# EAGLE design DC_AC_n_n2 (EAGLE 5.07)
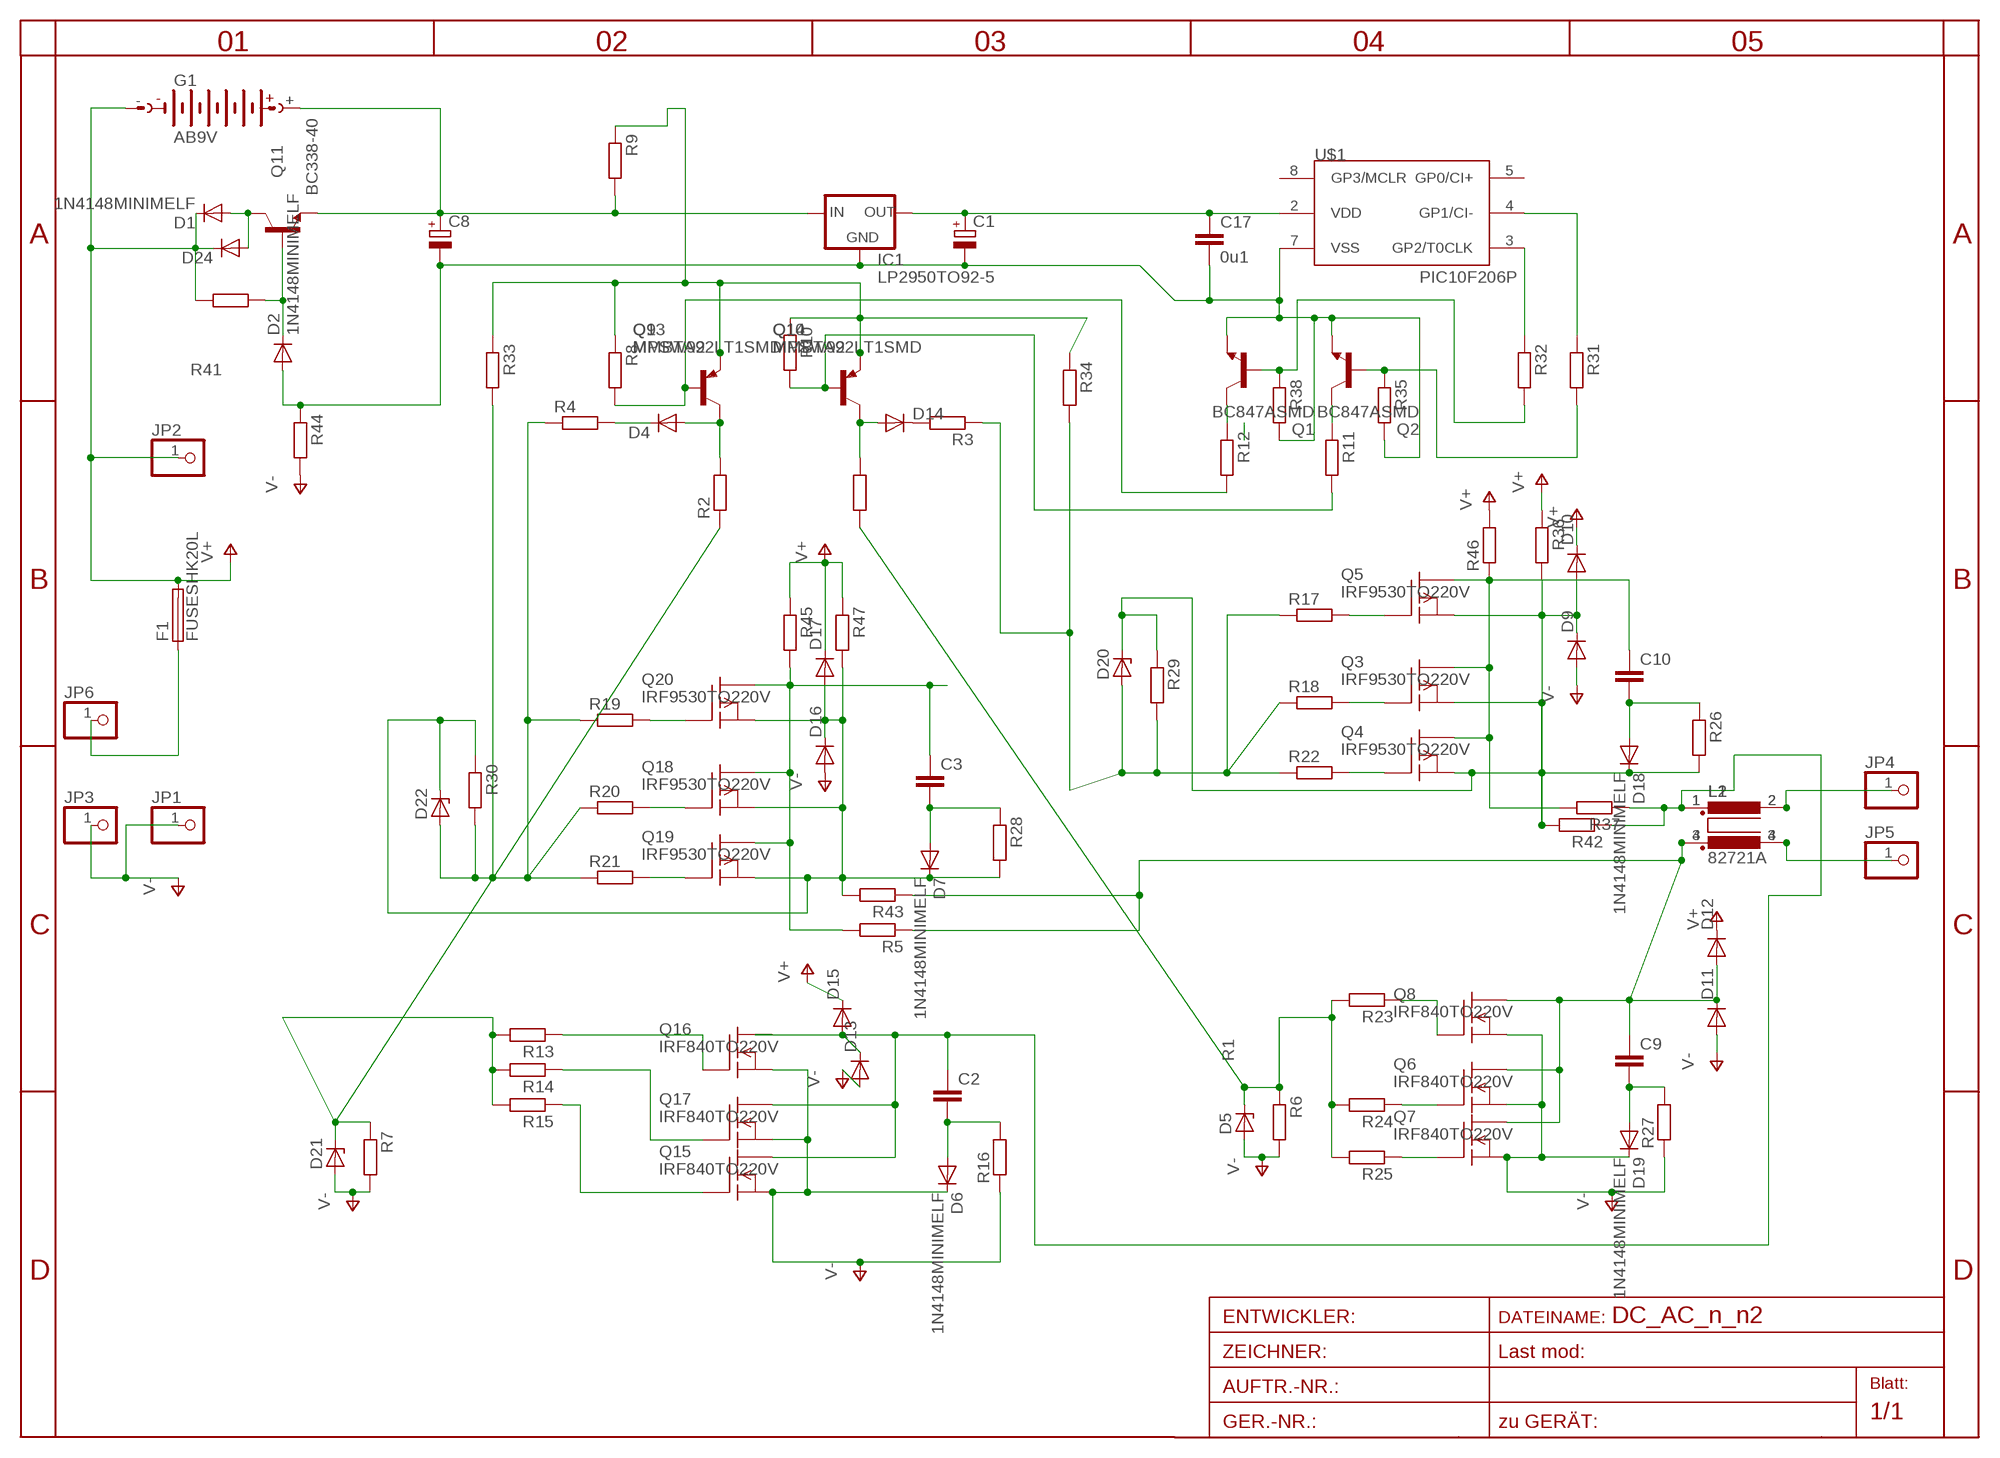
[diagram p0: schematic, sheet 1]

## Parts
C1  CPOL-EU5-13  [2,5-5-FLAT]
C2  C-EUC1812  [C1812]
C3  C-EUC1812K  [C1812K]
C8  CPOL-EUE2.5-7  [E2,5-7]
C9  C-EUC1812  [C1812]
C10  C-EUC1812K  [C1812K]
C17  0u1  C-EUC1206  [C1206]
D1  1N4148MINIMELF  [MINIMELF]
D2  1N4148MINIMELF  [MINIMELF]
D4  DIODE-SMB  [SMB]
D5  ZENER-DIODESOD80C  [SOD80C]
D6  1N4148MINIMELF  [MINIMELF]
D7  1N4148MINIMELF  [MINIMELF]
D9  DIODE-SMC  [SMC]
D10  DIODE-SMC  [SMC]
D11  DIODE-SMC  [SMC]
D12  DIODE-SMC  [SMC]
D13  DIODE-SMC  [SMC]
D14  DIODE-SMB  [SMB]
D15  DIODE-SMC  [SMC]
D16  DIODE-SMC  [SMC]
D17  DIODE-SMC  [SMC]
D18  1N4148MINIMELF  [MINIMELF]
D19  1N4148MINIMELF  [MINIMELF]
D20  ZENER-DIODESOD80C  [SOD80C]
D21  ZENER-DIODESOD80C  [SOD80C]
D22  ZENER-DIODESOD80C  [SOD80C]
D24  DIODE-D-7.5  [D-7.5]
F1  FUSESHK20L  [SHK20L]
G1  AB9V  [AB9V]
IC1  LP2950TO92-5  [T092-5]
JP1  PINHD-1X11MM6  [1X1MM8]
JP2  PINHD-1X11MM6  [1X1MM8]
JP3  PINHD-1X11MM6  [1X1MM8]
JP4  PINHD-1X14.5MM  [1X4MM5]
JP5  PINHD-1X14.5MM  [1X4MM5]
JP6  PINHD-1X11MM6  [1X1MM8]
L1  R1405VB2  [B2]
L2  82721A  [82721A]
Q1  BC847ASMD  [SOT23]
Q2  BC847ASMD  [SOT23]
Q3  IRF9530TO220V  [TO220V]
Q4  IRF9530TO220V  [TO220V]
Q5  IRF9530TO220V  [TO220V]
Q6  IRF840TO220V  [TO220V]
Q7  IRF840TO220V  [TO220V]
Q8  IRF840TO220V  [TO220V]
Q9  MPSW92  [TO92-CBE]
Q10  MPSW92  [TO92-CBE]
Q11  BC338-40  [TO92-EBC]
Q13  MMBTA92LT1SMD  [SOT23-BEC]
Q14  MMBTA92LT1SMD  [SOT23-BEC]
Q15  IRF840TO220V  [TO220V]
Q16  IRF840TO220V  [TO220V]
Q17  IRF840TO220V  [TO220V]
Q18  IRF9530TO220V  [TO220V]
Q19  IRF9530TO220V  [TO220V]
Q20  IRF9530TO220V  [TO220V]
R1  R-EU_0207/60  [0207/60]
R2  R-EU_0207/30  [0207/30]
R3  R-EU_0207/60  [0207/60]
R4  R-EU_0207/30  [0207/30]
R5  R-EU_0207/30  [0207/30]
R6  R-EU_R1206  [R1206]
R7  R-EU_R1206  [R1206]
R8  R-EU_R1206  [R1206]
R9  R-EU_0207/10  [0207/10]
R10  R-EU_R1206  [R1206]
R11  R-EU_R1206  [R1206]
R12  R-EU_R1206  [R1206]
R13  R-EU_R1206  [R1206]
R14  R-EU_R1206  [R1206]
R15  R-EU_R1206  [R1206]
R16  R-EU_R1206  [R1206]
R17  R-EU_R1206  [R1206]
R18  R-EU_R1206  [R1206]
R19  R-EU_R1206  [R1206]
R20  R-EU_R1206  [R1206]
R21  R-EU_R1206  [R1206]
R22  R-EU_R1206  [R1206]
R23  R-EU_R1206  [R1206]
R24  R-EU_R1206  [R1206]
R25  R-EU_R1206  [R1206]
R26  R-EU_R1206  [R1206]
R27  R-EU_R1206  [R1206]
R28  R-EU_R1206  [R1206]
R29  R-EU_R1206  [R1206]
R30  R-EU_R1206  [R1206]
R31  R-EU_R1206  [R1206]
R32  R-EU_R1206  [R1206]
R33  R-EU_0207/30  [0207/30]
R34  R-EU_0207/60  [0207/60]
R35  R-EU_R0805  [R0805]
R36  R-EU_0204/5  [0204/5]
R37  R-EU_0207/10  [0207/10]
R38  R-EU_R0805  [R0805]
R41  R-EU_R1206  [R1206]
R42  R-EU_0207/10  [0207/10]
R43  R-EU_0207/30  [0207/30]
R44  R-EU_R1206  [R1206]
R45  R-EU_0204/5  [0204/5]
R46  R-EU_0204/5  [0204/5]
R47  R-EU_0204/5  [0204/5]
U$1  PIC10F206P  [DIL8]

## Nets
AC1: JP4.1 L1.2 L2.2
AC2: JP5.1 L1.4 L2.3
BATT+: C8.+ G1.+ IC1.3(IN) Q11.E R9.2
FNGATE2: D4.C R4.2
N$1: F1.1A JP6.1
N$2: C3.1 Q18.2(D) Q19.2(D) Q20.2(D) R5.2 R45.2
N$3: Q1.3(C) R12.1
N$4: Q3.1(G) R18.2
N$5: C1.+ C17.1 IC1.1(OUT) U$1.2(VDD)
N$7: Q2.3(C) R11.1
N$9: D9.C D10.A D18.C D20.C Q3.3(S) Q4.3(S) Q5.3(S) R26.2 R29.1 R36.2 R42.2
N$10: D5.C R1.1 R6.1 R23.2 R24.2 R25.2
N$11: Q5.1(G) R17.2
N$13: Q15.1(G) R15.1
N$15: Q17.1(G) R14.1
N$16: Q9.B Q13.B R8.2 R12.2
N$18: D4.A Q9.C Q13.C R2.2
N$19: Q10.B Q14.B R10.2 R11.2
N$21: D14.A Q10.C Q14.C R1.2
N$22: Q16.1(G) R13.1
N$23: Q4.1(G) R22.2
N$24: C10.2 D18.A R26.1
N$25: Q7.1(G) R25.1
N$26: Q6.1(G) R24.1
N$27: Q8.1(G) R23.1
N$28: C9.2 D19.A R27.2
N$29: C2.2 D6.A R16.2
N$30: D7.C D16.C D17.A D22.C Q18.3(S) Q19.3(S) Q20.3(S) R28.2 R30.1 R43.2 R47.2
N$32: Q18.1(G) R20.2
N$33: Q19.1(G) R21.2
N$34: Q20.1(G) R19.2
N$35: C3.2 D7.A R28.1
N$36: D1.A D24.A Q11.C
N$38: D2.C Q11.B R41.1
N$39: R31.1 U$1.4(GP1/CI-)
N$42: Q2.1(B) R31.2 R35.1
N$43: R32.1 U$1.3(GP2/T0CLK)
N$45: Q1.1(B) R32.2 R38.1
N-GATE: D14.C R3.2
NDRAIN2: C2.1 D13.C D15.A L1.1 L2.1 Q15.2(D) Q17.2(D) R37.1 R42.1
NGATE2: D21.C R2.1 R7.1 R13.2 R14.2 R15.2
O1: C9.1 D11.C D12.A L1.3 L2.4 Q6.2(D) Q7.2(D) Q8.2(D) R5.1 R43.1
P-: C1.- C8.- C17.2 D2.A IC1.2(GND) Q1.2(E) Q2.2(E) R35.2 R38.2 R44.1 U$1.7(VSS)
PDRAIN1: C10.1 Q3.2(D) Q4.2(D) Q5.2(D) R37.2 R46.1
PGATE1: D20.A R3.1 R17.1 R18.1 R22.1 R29.2 R34.2
PGATE2: D22.A R4.1 R19.1 R20.1 R21.1 R30.2 R33.2
V+: D1.C D10.C D12.C D15.C D17.C D24.C F1.2A G1.- JP2.1 R36.1 R41.2 R45.1 R46.2 R47.1
V-: D5.A D6.C D9.A D11.A D13.A D16.A D19.C D21.A JP1.1 JP3.1 Q6.3(S) Q7.3(S) Q8.3(S) Q15.3(S) Q16.3(S) Q17.3(S) R6.2 R7.2 R16.1 R27.1 R44.2
VHIGH: Q9.E Q10.E Q13.E Q14.E R8.1 R9.1 R10.1 R33.1 R34.1
Unconnected: Q16.2(D) U$1.5(GP0/CI+) U$1.8(GP3/MCLR)

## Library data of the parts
C1 C8 = rcl-2:CPOL-EU: POLARIZED CAPACITOR, European symbol
C2 C3 C9 C10 C17 = rcl-2:C-EU: CAPACITOR, European symbol
D1 D2 D6 D7 D18 D19 = diode-1:1N4148: DIODE
D4 D9-D17 = diode:DIODE-: DIODE
D5 D20-D22 = diode:ZENER-DIODE: Z-Diode
D24 = diode-1:DIODE-: DIODE
F1 = fuse:FUSE: Fuse
G1 = battery:AB9V: 9-V BATTERY CLIP
IC1 = v-reg:LP2950?*: Source: http://cache.national.com/ds/LP/LP2950.pdf
JP1-JP6 = pinhead:PINHD-1X1: PIN HEADER
L1 = inductor-nkl:R1405V: Übertrager (verlustarm) bis typ. 400kHz Power transformer (low loss) up to typ. 400kHz
L2 = inductors:82721A: FILTER
Q1 Q2 = transistor-npn:BC847*: NPN Transistor
Q3-Q5 Q18-Q20 = transistor-fet:IRF9530: P-Channel Enhancement MOSFET (HEXFET); -100V; -12A; 0,3Ohm
Q6-Q8 Q15-Q17 = transistor-fet:IRF840: N-Channel Enhancement MOSFET (HEXFET); 500V; 8A; 0,85Ohm
Q9 Q10 = transistor-pnp:MPSW92*: PNP Transistror
Q11 = transistor-npn:BC338*: NPN Transistor
Q13 Q14 = transistor-pnp:MMBTA92*: PNP Transistror
R1-R38 R41-R47 = rcl-2:R-EU_: RESISTOR, European symbol
U$1 = microchip-5:PIC10F2*: uPC nW 0,25/0,5k Program Flash memory Comparator

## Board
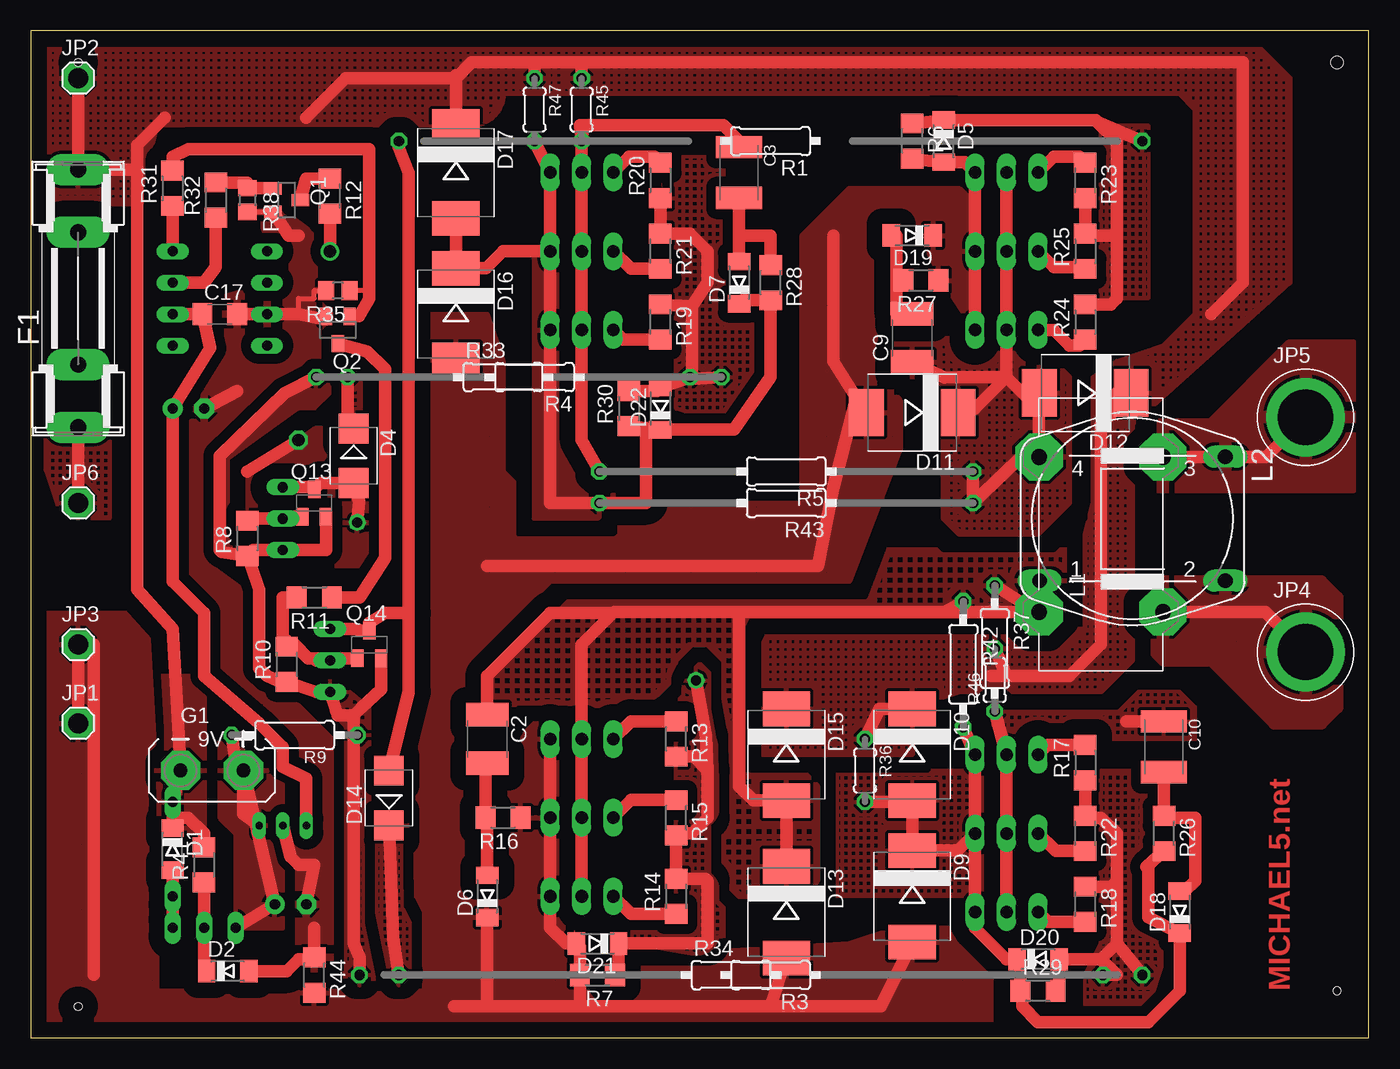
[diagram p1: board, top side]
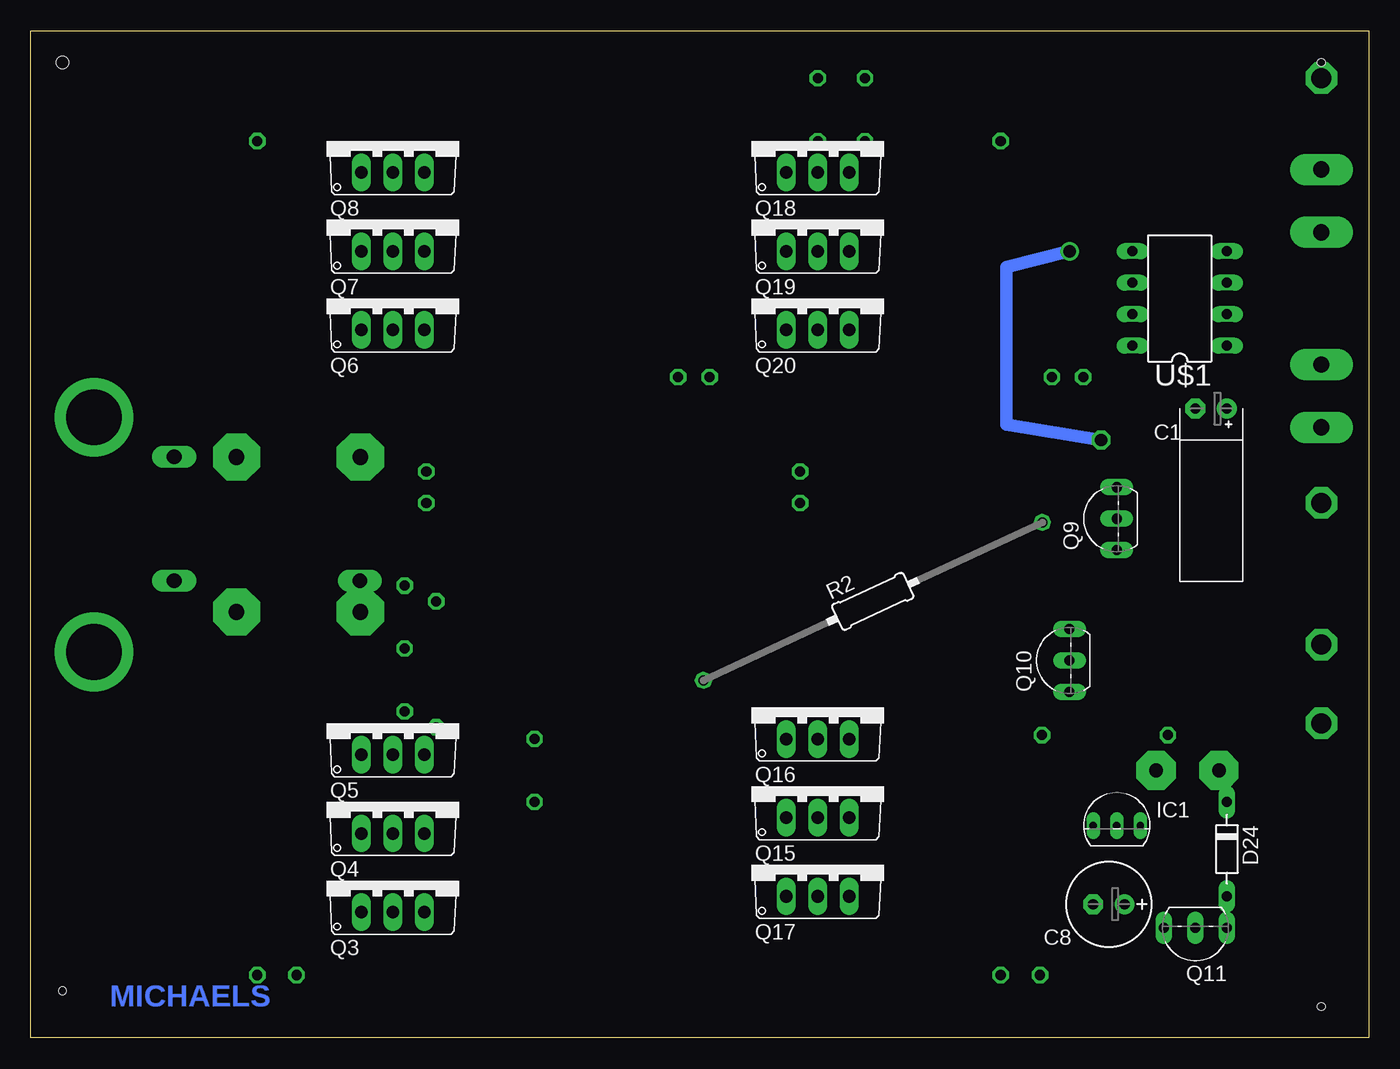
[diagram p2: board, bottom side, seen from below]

Size 107.95 x 81.28 mm. Coordinates in mm from the lower left corner, seen from the top.
Outline: 0,0 107.95,0 107.95,81.28 0,81.28 0,0
Copper layers (1*16): Top 0.035mm / dielectric 1.5mm / Bottom 0.035mm
Design rules "default *": minimum track width 12mil, minimum drill 24mil, track to track 8mil, track to pad 8mil, pad to pad 8mil, via to via 8mil, smd to smd 8mil, copper to edge 40mil, drill to drill 8mil, minimum pad ring 10mil, minimum via ring 8mil, stop-mask expansion 4mil, vias tented up to drill 0mil, thermal gap 10mil
Holes 0.6 mm at 3.81,78.74 3.81,2.54 105.41,3.81
Holes 1 mm at 105.41,78.74

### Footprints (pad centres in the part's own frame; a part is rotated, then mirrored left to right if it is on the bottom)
2,5-5-FLAT = drill 0.813 pad 1.6 round: + -1.27,0 | drill 0.813 pad 1.6 octagon: - 1.27,0
C1812 = smd 1.9 x 3.4: 1 -1.95,0; 2 1.95,0
C1812K = smd 1.8 x 3.7: 1 -2.05,0; 2 2.05,0
E2,5-7 = drill 0.813 pad 1.6 round: + -1.27,0 | drill 0.813 pad 1.6 octagon: - 1.27,0
C1206 = smd 1.6 x 1.8: 1 -1.4,0; 2 1.4,0
MINIMELF = smd 1.4 x 1.8: A 1.7,0; C -1.7,0
SMB = smd 2.4 x 2.4: A 2.2,0; C -2.2,0
SOD80C = smd 1.4 x 1.8: A 1.7,0; C -1.7,0
SMC = smd 2.8 x 3.8: A 3.7,0; C -3.7,0
D-7.5 = drill 0.813 long: A 3.81,0; C -3.81,0
SHK20L = drill 1.321 pad 2.54 long: 1A -10.414,0; 1B -5.334,0; 2A 10.414,0; 2B 5.334,0
AB9V = drill 1.118 pad 3.15 octagon: + 0,2.54; - 0,-2.54
T092-5 = drill 0.6 pad 0.813 long: 1 -1.905,0; 2 0,0; 3 1.905,0
1X1MM8 = drill 1.6 pad 2.54 octagon: 1 0,0
1X4MM5 = drill 4.5 pad 6.35 round: 1 0,0
B2 = drill 1.27 pad 3.81 octagon: 1 -6.25,5; 2 -6.25,-5; 3 6.25,5; 4 6.25,-5
82721A = drill 1.194 long: 1 7.493,5.004; 2 -7.493,5.004; 3 -7.493,-5.004; 4 7.493,-5.004
SOT23 = smd 1 x 1.4: 1 -0.95,-1.1; 2 0.95,-1.1; 3 0,1.1
TO220V = drill 1.016 long: 1 -2.54,-2.54; 2 0,-2.54; 3 2.54,-2.54
TO92-CBE = drill 0.813 long: B 0,0; C 2.54,0; E -2.54,0
TO92-EBC = drill 0.813 long: B 0,-1.27; C -2.54,-1.27; E 2.54,-1.27
SOT23-BEC = smd 1 x 1.4: B -0.95,-1.1; C 0,1.1; E 0.95,-1.1
0207/60 = drill 0.813 octagon: 1 -30,0; 2 30,0
0207/30 = drill 0.813 octagon: 1 -15.08,0; 2 15.08,0
R1206 = smd 1.6 x 1.803: 1 -1.422,0; 2 1.422,0
0207/10 = drill 0.813 octagon: 1 -5.08,0; 2 5.08,0
R0805 = smd 1.3 x 1.5: 1 -0.95,0; 2 0.95,0
0204/5 = drill 0.8 pad 1.27 octagon: 1 -2.54,0; 2 2.54,0
DIL8 = drill 0.8 long: 1 -3.81,-3.81; 2 -1.27,-3.81; 3 1.27,-3.81; 4 3.81,-3.81; 5 3.81,3.81; 6 1.27,3.81; 7 -1.27,3.81; 8 -3.81,3.81

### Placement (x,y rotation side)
C1  12.7,50.8 180 bottom
C2  36.83,24.13 270 top
C3  57.15,69.85 270 top
C8  20.95,10.79 180 bottom
C9  71.12,56.52 90 top
C10  91.44,23.5 270 top
C17  15.24,58.42 0 top
D1  11.43,15.24 270 top
D2  15.88,5.4 0 top
D4  26.03,46.99 270 top
D5  73.66,72.39 270 top
D6  36.83,11.43 90 top
D7  57.15,60.96 90 top
D9  71.12,11.43 270 top
D10  71.12,22.86 270 top
D11  71.12,50.48 180 top
D12  85.09,52.07 180 top
D13  60.96,10.16 270 top
D14  28.89,19.37 90 top
D15  60.96,22.86 270 top
D16  34.29,58.42 270 top
D17  34.29,69.85 270 top
D18  92.71,10.16 90 top
D19  71.12,64.77 180 top
D20  81.28,6.35 0 top
D21  45.72,7.62 180 top
D22  50.8,50.8 90 top
D24  11.43,15.24 270 bottom
F1  3.81,59.69 90 top
G1  14.61,21.59 270 top
IC1  20.32,17.14 0 bottom
JP1  3.81,25.4 0 top
JP2  3.81,77.47 0 top
JP3  3.81,31.75 0 top
JP4  102.87,31.15 0 top
JP5  102.87,50.1 0 top
JP6  3.81,43.18 0 top
L1  86.36,40.64 90 top
L2  88.9,41.91 180 top
Q1  20.64,67.63 270 top
Q2  24.77,57.15 180 top
Q3  78.74,12.7 0 bottom
Q4  78.74,19.05 0 bottom
Q5  78.74,25.4 0 bottom
Q6  78.74,59.69 0 bottom
Q7  78.74,66.04 0 bottom
Q8  78.74,72.39 0 bottom
Q9  20.32,41.91 90 bottom
Q10  24.13,30.48 90 bottom
Q11  13.97,7.62 180 bottom
Q13  22.86,43.18 0 top
Q14  27.3,31.75 0 top
Q15  44.45,20.32 0 bottom
Q16  44.45,26.67 0 bottom
Q17  44.45,13.97 0 bottom
Q18  44.45,72.39 0 bottom
Q19  44.45,66.04 0 bottom
Q20  44.45,59.69 0 bottom
R1  59.69,72.39 180 top
R2  40.01,35.24 25 bottom
R3  59.69,5.08 180 top
R4  40.64,53.34 180 top
R5  60.96,45.72 180 top
R6  71.12,72.39 270 top
R7  45.72,5.08 180 top
R8  17.46,40.32 90 top
R9  21.27,24.45 180 top
R10  20.64,30.16 90 top
R11  22.86,35.56 180 top
R12  24.13,67.94 270 top
R13  52.07,24.13 270 top
R14  52.07,11.43 90 top
R15  52.07,17.78 270 top
R16  38.1,17.78 180 top
R17  85.09,22.23 90 top
R18  85.09,10.79 270 top
R19  50.8,57.78 270 top
R20  50.8,69.22 90 top
R21  50.8,63.5 270 top
R22  85.09,16.51 270 top
R23  85.09,69.22 270 top
R24  85.09,57.78 90 top
R25  85.09,63.5 90 top
R26  91.44,16.51 270 top
R27  71.82,61.15 180 top
R28  59.69,60.96 270 top
R29  81.28,3.81 0 top
R30  48.26,50.8 90 top
R31  11.43,68.58 90 top
R32  14.92,67.63 90 top
R33  38.1,53.34 0 top
R34  56.52,5.08 0 top
R35  24.77,60.33 180 top
R36  67.31,21.59 270 top
R37  77.79,31.43 270 top
R38  17.46,67.63 270 top
R41  13.97,13.97 90 top
R42  75.25,30.16 270 top
R43  60.96,43.18 180 top
R44  22.86,5.08 270 top
R45  44.45,74.93 270 top
R46  77.79,28.89 90 top
R47  40.64,74.93 270 top
U$1  15.24,59.69 90 bottom

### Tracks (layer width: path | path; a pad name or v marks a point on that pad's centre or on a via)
AC1
  Top 1.016: L1.2 99.63,34.39 JP4.1
  pour Top (isolate 1.27, rank 3, hatched): 90.17,36.83 104.14,36.83 105.41,35.56 105.41,26.67 104.14,25.4 100.33,25.4 95.25,30.48 91.44,30.48 90.17,31.75
AC2
  Top 1.016: L1.4 99.66,46.89 JP5.1
  pour Top (isolate 0.813, rank 3, hatched): 88.9,48.26 90.17,49.53 95.25,49.53 101.6,55.88 106.68,55.88 106.68,44.45 88.9,44.45
BATT+
  Top 1.016: Q11.E C8.+ G1.+ | G1.+ 16.51,22.23 R9.2 | IC1.3 17.14,18.1 G1.+
  pour Top (isolate 0.61): 15.24,24.13 15.24,19.05 15.24,17.78 16.51,16.51 16.51,8.89 20.32,8.89 20.32,21.59
FNGATE2
  Top 1.016: R4.2 25.56,50.3 D4.C
  pour Top (isolate 1.27, rank 5, hatched): 24.13,53.34 25.4,54.61 27.94,54.61 27.94,48.26 24.13,48.26
N$1
  Top 1.016: JP6.1 F1.1A
  pour Top (isolate 0.813, rank 3, hatched): 0,48.26 6.35,48.26 6.35,41.91 2.54,41.91 1.27,45.72
N$2
  Top 1.016: R45.2 Q18.2 Q19.2 Q20.2 44.45,48.26 R5.2 | R45.2 44.3,73.66 | C3.1 57.15,72.39 55.88,73.66 44.6,73.66 R45.2
N$3
  Top 1.016: Q1.3 22.21,69.37 R12.1
N$4
  Top 1.016: R18.2 82.07,9.37 Q3.1
N$5
  Top 1.016: U$1.2 C17.1 14.47,55.69 C1.+ 11.43,36.83 13.97,34.29 13.97,29.21 18.41,25.4 20.32,23.5 20.31,21.9 22.23,20.94 IC1.1
N$7
  Top 1.016: R11.1 26.52,35.56 28.58,38.73 28.58,53.98 27.13,55.41 Q2.3
N$9
  Top 1.016: Q4.3 Q3.3 76.2,8.89 78.74,6.35 D20.C 79.86,6.07 R29.1 80.01,3.66 80.01,2.54 81.28,1.27 90.17,1.27 92.71,3.81 D18.C 90.17,9.73 90.17,13.97 90.02,13.82 R26.2 | Q4.3 Q5.3 R42.2 | Q4.3 74.82,15.13 D9.C 71.12,19.05 | 71.12,19.05 R36.2 | 71.12,19.05 D10.A
  pour Top (isolate 1.27, rank 4, hatched): 64.77,21.59 77.47,21.59 77.47,11.43 64.77,11.43
N$10
  Top 1.016: R24.2 87.15,59.21 87.63,59.69 87.63,64.77 | 87.63,64.77 85.24,64.77 R25.2 R23.2 | 86.04,73.98 87.63,72.39 87.63,64.77 | R6.1 D5.C 85.93,74.09 86.04,73.98 | 86.04,73.98 R1.1
  pour Top (isolate 0.813, rank 3, hatched): 86.36,73.66 90.17,73.66 90.17,59.69 86.36,59.69
N$11
  Top 1.016: R17.2 82.07,23.65 Q5.1
N$13
  Top 1.016: R15.1 48.41,19.2 Q15.1
N$15
  Top 1.016: R14.1 48.41,10.01 Q17.1
N$16  (via drill 1)
  Top 1.016: R8.2 17.93,41.91 Q9.B 20.49,42.08 Q13.B | v24.13,63.5 R12.2 | 17.46,45.72 v21.59,48.26
  Bottom 1.016: v24.13,63.5 29.21,62.23 29.21,49.53 v21.59,48.26
  pour Top (isolate 1.27, rank 4): 21.59,50.8 24.13,50.8 24.13,45.72 16.51,41.91 17.78,46.99
N$18
  Top 1.016: R2.2 26.47,43.32 D4.A 23.37,44.79 Q13.C 22.69,44.45 Q9.C
  pour Top (isolate 0.813, rank 5): 26.67,45.72 27.94,45.72 29.21,39.37 26.67,38.1 24.13,38.1 24.13,44.45
N$19
  Top 1.016: 23.01,30.48 Q10.B 23.03,30.65 | 23.03,30.65 Q14.B | R11.2 20.32,35.56 20.32,32.07 20.64,32.07 R10.2 20.8,31.75 21.27,31.75 22.37,30.65 23.03,30.65
N$21
  Top 1.016: R1.2 29.69,71.91 30.48,69.85 30.48,34.29 | 30.48,34.29 28.58,34.29 27.3,33.48 Q14.C 25.87,33.02 Q10.C | D14.A 30.48,27.94 30.48,34.29
N$22
  Top 1.016: R13.1 48.41,25.55 Q16.1
N$23
  Top 1.016: R22.2 82.7,15.09 Q4.1
N$24
  Top 1.016: D18.A 93.14,11.86 93.98,12.7 93.98,17.78 91.59,17.78 R26.1 C10.2
N$25
  Top 1.016: Q7.1 82.55,62.23 84.94,62.23 R25.1
N$26
  Top 1.016: Q6.1 82.55,57.15 83.82,55.88 84.61,55.88 R24.1
N$27
  Top 1.016: Q8.1 82.55,71.12 84.61,71.12 R23.1
N$28
  Top 1.016: D19.A 69.85,64.77 69.85,60.96 70.4,60.96 R27.2 69.85,61.15 69.85,58.42 71.12,58.42 C9.2
N$29
  Top 1.016: C2.2 36.68,22.18 R16.2 36.83,17.78 D6.A
N$30
  Top 1.016: Q19.3 Q18.3 R47.2 | Q19.3 Q20.3 41.91,43.18 R43.2 49.64,43.18 49.64,49.23 | 49.64,49.23 R30.1 | 49.64,49.23 D22.C 56.72,49.1 59.69,53.34 R28.2 57.43,59.54 D7.C | D17.A D16.C 36.72,62.12 38.1,63.5 Q19.3
  pour Top (isolate 1.27): 43.18,48.26 43.18,46.99 44.45,45.72 45.72,45.72 46.99,44.45 46.99,43.18 45.72,41.91 40.64,41.91 40.64,63.5 43.18,63.5
N$32
  Top 1.016: Q18.1 48.26,71.12 50.32,71.12 R20.2
N$33
  Top 1.016: R21.2 48.41,62.08 Q19.1
N$34
  Top 1.016: R19.2 47.78,56.36 Q20.1
N$35
  Top 1.016: D7.A 57.15,64.77 | 57.15,64.77 C3.2 | R28.1 59.69,64.77 57.15,64.77
N$36
  Top 1.016: D1.A D24.A Q11.C
N$38
  Top 1.016: R41.1 Q11.B 13.97,5.6 D2.C
N$39
  Top 1.016: U$1.4 R31.1
N$42
  Top 0.406: R35.1 27.15,60.33 27.15,59.42
  Top 1.016: R31.2 11.43,71.12 12.7,71.75 27.3,71.75 27.3,59.69 27.15,59.42 26.5,58.25 Q2.1
N$43
  Top 1.016: U$1.3 13.97,60.96 14.92,62.23 R32.1
N$45
  Top 1.016: R32.2 17.46,69.05 R38.1 Q1.1
N-GATE
  Top 1.016: D14.C 29.21,8.1 R3.2
  pour Top (isolate 0.813, rank 3, hatched): 27.94,17.78 30.48,17.78 31.75,8.89 31.75,3.81 29.21,3.81 27.94,10.16
NDRAIN2
  Top 1.016: D13.C D15.A 58.31,19.16 57.15,20.32 57.15,34.39 | 57.15,34.39 47.09,34.39 46.99,34.29 | 57.15,34.39 L1.1 | 46.99,34.29 44.45,31.75 Q15.2 Q17.2 | R42.1 73.79,34.44 L1.1 | C2.1 36.83,29.21 41.91,34.29 46.99,34.29 | R37.1 81.28,34.31 L1.1
  pour Top (isolate 1.27, rank 3, hatched): 35.56,26.67 40.64,26.67 43.18,24.13 46.99,24.13 52.07,29.21 52.07,30.48 53.34,31.75 54.61,31.75 55.88,30.48 55.88,12.7 57.15,11.43 62.23,11.43 63.5,12.7 63.5,20.32 62.23,21.59 59.05,21.59 59.05,30.48 59.69,31.75 83.82,31.75 83.82,39.37 66.04,39.37 63.5,36.83 41.91,36.83 38.1,33.02
NGATE2
  Top 1.016: R13.2 53.49,22.71 54.61,21.59 | 54.61,21.59 54.61,17.78 53.34,16.51 52.22,16.51 R15.2 R14.2 54.46,12.85 54.61,12.7 54.61,7.62 D21.C 47.42,5.36 R7.1 | R2.1 54.49,24.33 54.61,21.59
  pour Top (isolate 0.813, rank 4, hatched): 52.07,29.21 54.61,33.02 55.88,31.75 55.88,6.35 48.26,7.62 48.26,8.89 52.07,8.89
O1
  Top 1.016: 81.36,48.26 L1.3 | 81.36,48.26 81.36,50.72 | 81.36,50.72 78.74,53.34 | 78.74,53.34 Q6.2 Q7.2 Q8.2 | 81.36,48.26 R43.1 R5.1 | C9.1 73.7,53.3 74.93,53.34 78.74,53.34 | D11.C 76.2,50.8 78.74,53.34 | D12.A 81.36,52.07 81.36,50.72
  pour Top (isolate 1.27, hatched): 69.85,57.15 80.01,57.15 83.82,53.34 83.82,43.18 81.28,40.64 74.93,40.64 73.66,41.91 73.66,52.07 73.02,53.34 69.85,53.34
P-
  Top 0.406: R35.2 22.86,60.33 22.86,59.69 21.59,59.69 21.59,58.42 | R38.2 Q1.2
  Top 1.016: C1.- 16.64,52.2 | C17.2 U$1.7 21.59,58.42 23.18,58.1 | Q1.2 20.81,64.77 21.59,64.77 | D2.A 20.64,5.4 21.59,6.35 22.71,6.35 R44.1 22.86,8.89 | IC1.2 20.95,14.61 21.59,13.97 22.86,13.97 C8.-
  pour Top (isolate 0.813, rank 2, hatched): 18.41,66.67 20.32,66.67 22.86,64.77 22.86,59.69 25.4,57.15 22.86,54.61 20.32,53.34 14.29,48.26 14.29,38.1 17.78,35.56 17.78,30.48 24.13,24.13 24.13,5.08 22.86,5.08 21.59,6.35 21.59,12.7 19.05,13.97 19.05,15.24 20.32,16.51 20.32,24.13 16.51,24.13 16.51,25.4 15.24,26.67 15.24,33.02 11.43,36.83 11.43,52.07 12.7,53.34 13.97,53.34 15.24,54.61 15.24,59.69 20.32,60.96
PDRAIN1
  Top 1.016: Q3.2 Q4.2 Q5.2 R37.2 | 88.41,25.55 C10.1
  pour Top (isolate 1.27, rank 4, hatched): 93.98,26.67 92.71,27.94 78.74,27.94 77.47,26.67 77.47,24.13 80.01,24.13 93.98,24.13
PGATE1
  Top 1.016: R17.1 R22.1 85.24,17.78 86.36,17.78 87.63,16.51 87.63,12.7 | R18.1 87.15,12.22 87.63,12.7 | 86.36,6.35 D20.A 82.98,4.09 R29.2 | 86.36,6.35 87.63,7.62 | 87.63,7.62 87.63,12.7 | R34.2 87.63,5.08 86.36,6.35 | 87.63,7.62 R3.1
  pour Top (isolate 0.813, rank 4, hatched): 86.36,21.59 90.17,21.59 91.44,6.35 90.17,2.54 85.09,2.54 85.09,5.08 86.36,7.62
PGATE2
  Top 1.016: R20.1 R21.1 53.19,64.92 54.61,63.5 54.61,60.96 53.34,59.05 | 53.34,59.05 R19.1 | 53.34,53.34 D22.A 50.52,52.22 R30.2 | 53.34,53.34 53.34,59.05 | 53.34,53.34 53.34,53.18 R4.1 | 53.34,53.34 R33.2
  pour Top (isolate 0.813, rank 4, hatched): 50.8,71.12 55.88,71.12 55.88,58.42 58.42,58.42 58.42,52.07 55.88,49.53 52.07,50.8 52.07,59.69
V+
  Top 1.016: 95.25,58.42 97.79,60.96 97.79,78.74 44.45,78.74 | 40.64,78.74 44.45,78.74 | 44.45,78.74 R45.1 | D12.C 87.63,52.07 87.63,50.8 86.36,49.53 86.36,31.75 83.82,29.21 78.74,29.21 | 40.64,78.74 R47.1 | 78.74,29.21 R46.2 | 78.74,29.21 77.47,29.21 | D10.C 68.47,26.56 R36.1 | 8.57,69.85 8.57,36.2 11.43,33.02 G1.- D24.C 11.43,17.78 | 8.57,69.85 8.57,72.07 10.79,74.3 | 34.29,77.47 34.29,77.72 | 34.29,77.47 D17.C | 34.29,77.47 35.56,78.74 40.64,78.74 | 22.23,74.3 25.4,77.47 34.29,77.47 | 8.57,69.85 8.32,70.1 F1.2A JP2.1 | D1.C 11.43,17.78 | R41.2 13.97,16.51 12.7,17.78 11.43,17.78
  pour Top (isolate 1.27, rank 2, hatched): 1.27,80.01 99.06,80.01 101.6,77.47 101.6,60.96 88.9,49.53 88.9,30.48 86.36,27.94 74.93,27.94 71.12,26.67 71.12,22.86 59.05,22.86 59.05,31.75 59.69,33.02 85.09,33.02 85.09,40.64 85.72,43.18 85.72,53.34 87.63,54.61 91.44,55.88 93.98,58.42 93.98,74.93 92.71,76.2 38.1,76.2 arc-90 35.56,73.66 10.16,73.66 8.89,68.58 8.89,67.31 1.27,67.31
  pour Top (isolate 0.61, rank 3): 10.16,29.21 13.97,29.21 13.97,15.24 11.43,16.51 10.16,17.78
V-
  Top 1.016: Q6.3 Q7.3 Q8.3 75.36,70.69 D5.A 71.96,70.84 R6.2 | Q16.3 Q15.3 Q17.3 41.91,8.89 43.18,7.62 D21.A 44.3,7.34 R7.2 44.3,2.69 44.45,2.54 | 66.62,51.64 64.77,44.45 63.5,38.1 36.83,38.1 | 66.62,51.64 64.77,54.61 64.77,64.77 | D9.A 68.58,2.54 59.69,2.54 | 34.14,2.54 36.83,2.54 | 36.83,2.54 44.45,2.54 | 44.45,2.54 59.69,2.54 | 59.69,2.54 D13.A | D11.A 66.62,50.8 66.62,51.64 | 36.83,2.54 D6.C | JP1.1 JP3.1 5.08,31.75 5.08,5.08
  pour Top (isolate 1.27, rank 2, hatched): 0,34.29 10.16,34.29 10.16,3.81 31.75,3.81 31.75,10.16 31.12,11.43 30.48,54.61 31.75,58.42 36.83,58.42 38.1,54.61 38.1,45.72 40.64,43.18 62.23,43.18 62.23,64.77 66.04,68.58 74.93,68.58 76.2,67.31 76.2,57.15 73.66,60.96 72.39,63.5 68.58,63.5 68.58,53.34 70.17,51.44 70.17,47.62 66.04,36.83 41.91,36.83 35.56,30.48 34.29,26.67 34.29,24.13 35.56,22.86 38.1,22.86 40.64,25.4 43.18,25.4 43.18,10.16 44.45,6.35 66.04,7.62 69.85,8.89 77.47,8.89 77.47,1.27 76.2,0 8.89,0 0,1.27
VHIGH
  Top 1.016: R8.1 17.93,39.37 Q9.E 23.81,39.37 23.81,41.76 Q13.E | R33.1 20.48,52.07 15.24,46.99 15.24,39.37 15.39,39.22 R8.1 | R34.1 26.52,6.5 26.03,7.62 26.03,26.04 | Q14.E 28.26,28.11 26.67,26.67 26.03,26.04 | 26.03,26.04 24.77,26.04 Q10.E 23.01,27.94 R10.1 20.49,28.57 19.05,29.21 18.41,29.84 18.41,36.2 17.78,38.1 R8.1
  pour Top (isolate 0.813, rank 3): 17.78,39.37 15.24,39.37 15.24,46.99 22.86,54.61 24.13,53.34 24.13,52.07 22.86,50.8 21.59,50.8 15.88,46.67 15.88,39.69
  pour Top (isolate 0.813, rank 4, hatched): 24.13,29.21 27.3,26.67 27.3,13.97 27.94,3.81 25.4,3.81

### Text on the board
Top: MICHAEL5.net
Bottom: MICHAELS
